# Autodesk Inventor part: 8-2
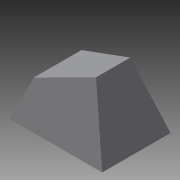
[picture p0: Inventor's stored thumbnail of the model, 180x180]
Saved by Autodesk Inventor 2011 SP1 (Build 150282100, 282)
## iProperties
Created: 2014-01
Part Number: 8-2
Document SubType Name: Modeling
Designer: Administrator
Density: 1 g/cm^3
Author: Administrator
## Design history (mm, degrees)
sketch "草图1"
  geometry: L1 (-19, 14)-(19, 14); L2 (19, 14)-(19, -14); L3 (19, -14)-(-19, -14); L4 (-19, -14)-(-19, 14); 3 further points
  constraints: 8 end point, 2 midpoint, 2 parallel, 1 horizontal, 1 horizontal alignment, 1 perpendicular, 1 vertical alignment
  dimensions: "d0" = 38 distance of L2.end L3.end; "d1" = 28 distance of L1.end L2.end
sketch "草图2"
  geometry: 2 further points
  dimensions: "d2" = 51 distance of point (0, 0) point (0, 51)
feature "放样1" sketch "草图1", "草图2" dims "d3" = 0, "d4" = 90 deg, "d5" = 0, "d6" = 90 deg
sketch "草图3"
  geometry: L1 (0, 51)-(19, 0) reference; L2 (0, 51)-(-19, 0) reference; L3 (13.255, 15.421)-(-9.5, 25.5); 1 further point
  constraints: 2 end point, 1 midpoint, 1 point on line
extrude "拉伸1" cut sketch "草图3" stored distance "d7" = 10; taper "d8" = 0 deg
node "实体1"
